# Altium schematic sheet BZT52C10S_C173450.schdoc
size 127 x 101 mm
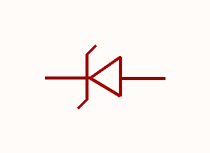
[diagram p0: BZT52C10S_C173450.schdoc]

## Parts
D?  bzt52c10s_c173450  [SOD-323_L1.8-W1.3-LS2.5-RD]  (value not drawn)

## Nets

Not connected (* = marked no-connect by the designer): D? 1(K) 2(A)

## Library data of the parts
D? = bzt52c10s_c173450: 二极管配置:1个独立式;稳压值(标称值):10V;稳压值(范围值):9.4V~10.6V;耗散功率(Pd):200mW;; Manufacturer: MDD(辰达半导体); AddInBom: yes; ModelId: db63db13d9e342eb939127d413d6200b; ModelTransform: 104.3305,51.181,0,0,0,0,0,-0.004,0; Diode Configuration: 1个独立式; Zener Voltage(Nom): 10V; Reverse Leakage Current (Ir): 100nA@7V; Pd - Power Dissipation: 200mW; Impedance(Zzt): 30Ω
